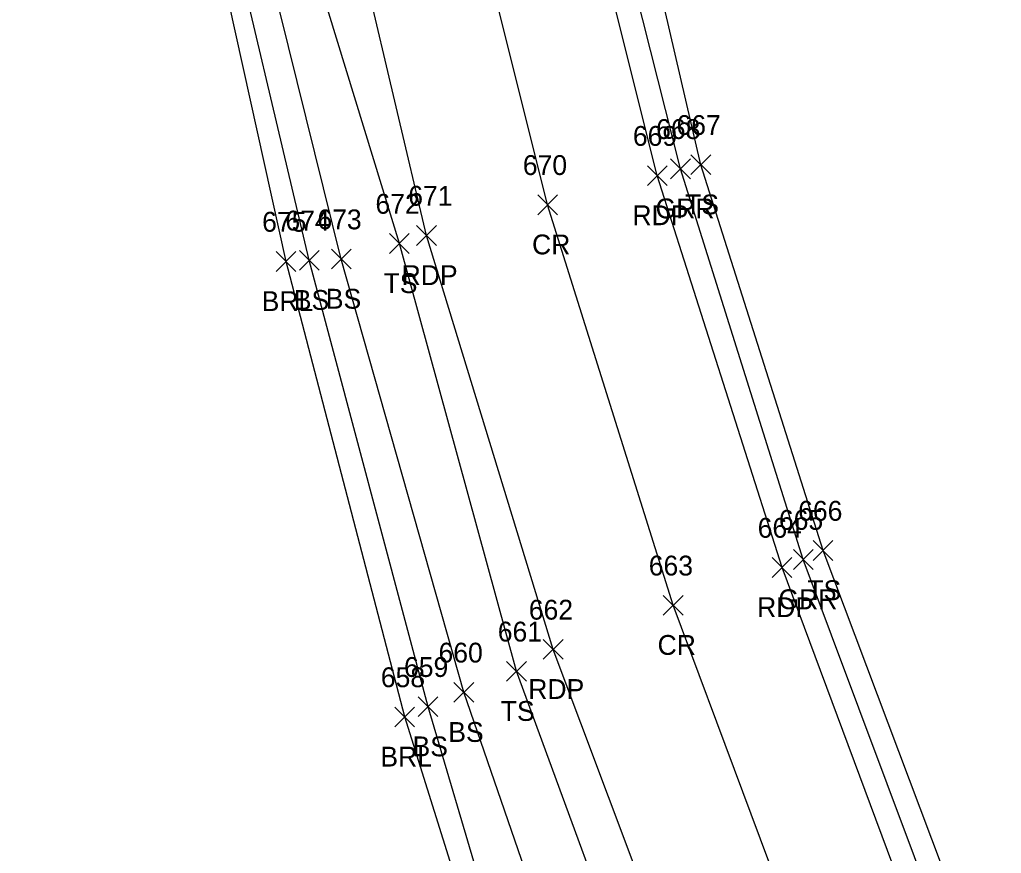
# Model space of a CAD drawing. Extents: x 1879695 to 1880991, y 836466 to 845172.
# Drawn here: x 1879788.6 to 1879887.6, y 844501 to 844585 of the extents above; entities that cross this region are included whole.
import ezdxf

# ---------------------------------------------------------------- set-up
doc = ezdxf.new("R2010")
doc.units = 0
for name, color, linetype in [('L_A', 7, 'Continuous'), ('L_I', 7, 'Continuous'), ('L_TIC', 7, 'Continuous'), ('LABL', 7, 'Continuous'), ('LELB', 7, 'Continuous'), ('P_A', 7, 'Continuous'), ('P_I', 7, 'Continuous'), ('P_TIC', 7, 'Continuous'), ('PET', 7, 'Continuous'), ('PRC', 7, 'Continuous'), ('R_A', 7, 'Continuous'), ('R_I', 7, 'Continuous'), ('R_TIC', 7, 'Continuous'), ('RGR', 7, 'Continuous')]:
    doc.layers.add(name, color=color, linetype=linetype)

msp = doc.modelspace()

# ---------------------------------------------------------------- linework, layer by layer
at = {"layer": 'L_TIC'}
for points in [[(1879856.268, 844569.414), (1879858.268, 844571.414)], [(1879858.268, 844569.414), (1879856.268, 844571.414)], [(1879825.856, 844561.475), (1879827.856, 844563.475)], [(1879827.856, 844561.475), (1879825.856, 844563.475)], [(1879814.427, 844559.662), (1879816.427, 844561.662)], [(1879816.427, 844559.662), (1879814.427, 844561.662)], [(1879816.772, 844559.782), (1879818.772, 844561.782)], [(1879818.772, 844559.782), (1879816.772, 844561.782)], [(1879820.001, 844559.904), (1879822.001, 844561.904)], [(1879822.001, 844559.904), (1879820.001, 844561.904)], [(1879868.595, 844530.526), (1879870.595, 844532.526)], [(1879870.595, 844530.526), (1879868.595, 844532.526)], [(1879837.676, 844518.351), (1879839.676, 844520.351)], [(1879839.676, 844518.351), (1879837.676, 844520.351)], [(1879832.354, 844516.232), (1879834.354, 844518.232)], [(1879834.354, 844516.232), (1879832.354, 844518.232)], [(1879828.748, 844514.782), (1879830.748, 844516.782)], [(1879830.748, 844514.782), (1879828.748, 844516.782)], [(1879826.398, 844513.749), (1879828.398, 844515.749)], [(1879828.398, 844513.749), (1879826.398, 844515.749)]]:
    msp.add_lwpolyline(points, dxfattribs=at)
at = {"layer": 'LABL'}
msp.add_lwpolyline([(1879838.844, 844478.292), (1879827.398, 844514.749), (1879815.427, 844560.662), (1879806.766, 844599.893), (1879795.175, 844646.787), (1879789.744, 844677.989)], dxfattribs=at)
at = {"layer": 'LELB'}
for points in [[(1879840.739, 844478.66), (1879829.748, 844515.782), (1879817.772, 844560.782), (1879808.572, 844599.661), (1879797.58, 844646.674), (1879792.294, 844679.837), (1879789.079, 844683.631), (1879788.581, 844684.774), (1879788.558, 844689.105), (1879790.666, 844689.028), (1879791.227, 844732.995), (1879790.397, 844776.52), (1879790.901, 844833.288), (1879792.574, 844880.834), (1879794.656, 844928.507), (1879796.597, 844970.46), (1879795.452, 845013.86), (1879797.689, 845051.682), (1879797.82, 845087.621), (1879798.32, 845126.29), (1879799.706, 845166.006)], [(1879892.858, 844475.325), (1879883.809, 844493.877), (1879869.595, 844531.526), (1879857.268, 844570.414), (1879848.001, 844610.419), (1879840.978, 844651.693), (1879836.739, 844689.332), (1879832.498, 844735.025), (1879831.422, 844779.249), (1879830.938, 844828.137), (1879831.115, 844883.886), (1879831.784, 844926.928), (1879832.166, 844972.314), (1879832.241, 845014.045), (1879832.594, 845051.892), (1879833.365, 845086.821), (1879834.056, 845125.479), (1879835.582, 845163.134)], [(1880237.645, 844030.169), (1880225.552, 844045.248), (1880203.194, 844067.938), (1880175.04, 844095.38), (1880141.552, 844124.236), (1880111.589, 844152.125), (1880079.671, 844179.091), (1880044.886, 844208.162), (1880013.498, 844237.535), (1880003.345, 844247.815), (1879979.157, 844270.618), (1879948.511, 844300.872), (1879928.971, 844335.674), (1879901.59, 844373.869), (1879881.388, 844405.749), (1879863.368, 844445.075), (1879846.411, 844479.406), (1879833.354, 844517.232), (1879821.001, 844560.904), (1879811.239, 844600.263), (1879800.643, 844646.711), (1879794.198, 844680.159), (1879792.03, 844683.602), (1879789.079, 844683.631)], [(1880243.526, 844023.942), (1880226.641, 844046.282), (1880204.681, 844069.124), (1880177.193, 844097.387), (1880144.147, 844127.373), (1880114.344, 844154.462), (1880082.653, 844181.379), (1880047.531, 844211.782), (1880015.321, 844240.115), (1879982.289, 844271.841), (1879951.965, 844303.04), (1879930.285, 844336.913), (1879904.081, 844374.32), (1879883.922, 844406.902), (1879866.984, 844446.021), (1879852.226, 844482.486), (1879838.676, 844519.351), (1879826.856, 844562.475), (1879815.218, 844600.521)]]:
    msp.add_lwpolyline(points, dxfattribs=at)
at = {"layer": 'P_TIC'}
for points in [[(1879851.877, 844568.319), (1879853.877, 844570.319)], [(1879853.877, 844568.319), (1879851.877, 844570.319)], [(1879840.808, 844565.377), (1879842.808, 844567.377)], [(1879842.808, 844565.377), (1879840.808, 844567.377)], [(1879828.601, 844562.282), (1879830.601, 844564.282)], [(1879830.601, 844562.282), (1879828.601, 844564.282)], [(1879864.456, 844528.814), (1879866.456, 844530.814)], [(1879866.456, 844528.814), (1879864.456, 844530.814)], [(1879853.471, 844525.007), (1879855.471, 844527.007)], [(1879855.471, 844525.007), (1879853.471, 844527.007)], [(1879841.372, 844520.559), (1879843.372, 844522.559)], [(1879843.372, 844520.559), (1879841.372, 844522.559)]]:
    msp.add_lwpolyline(points, dxfattribs=at)
at = {"layer": 'PET'}
for points in [[(1880269.75, 844039.673), (1880250.269, 844065.902), (1880225.972, 844090.312), (1880195.983, 844117.546), (1880162.099, 844148.126), (1880132.616, 844174.702), (1880101.364, 844203.027), (1880066.936, 844232.591), (1880034.498, 844263.161), (1880004.089, 844293.645), (1879978.17, 844323.395), (1879954.458, 844354.819), (1879930.757, 844391.373), (1879912.368, 844423.118), (1879894.175, 844458.904), (1879879.413, 844492.336), (1879865.456, 844529.814), (1879852.877, 844569.319), (1879843.172, 844608.033)], [(1880246.168, 844024.856), (1880229.346, 844048.536), (1880207.668, 844072.229), (1880179.649, 844099.993), (1880146.479, 844130.195), (1880116.3, 844156.757), (1880085.614, 844184.855), (1880050.42, 844215.316), (1880017.65, 844245.828), (1879986.989, 844277.133), (1879959.044, 844308.586), (1879934.196, 844340.79), (1879910.262, 844378.732), (1879891.139, 844411.431), (1879872.359, 844448.445), (1879856.332, 844484.427), (1879842.372, 844521.559), (1879829.601, 844563.282), (1879820.426, 844602.227)]]:
    msp.add_lwpolyline(points, dxfattribs=at)
at = {"layer": 'PRC'}
msp.add_lwpolyline([(1880256.848, 844032.042), (1880238.908, 844056.201), (1880216.704, 844080.653), (1880187.273, 844108.926), (1880154.229, 844138.823), (1880124.193, 844165.482), (1880092.742, 844193.415), (1880058.564, 844223.39), (1880025.993, 844253.924), (1879995.138, 844285.409), (1879968.795, 844316.238), (1879945.09, 844347.911), (1879920.67, 844385.195), (1879902.454, 844417.136), (1879883.724, 844454.205), (1879868.528, 844488.383), (1879854.471, 844526.007), (1879841.808, 844566.377), (1879832.134, 844605.001)], dxfattribs=at)
at = {"layer": 'R_TIC'}
for points in [[(1879854.214, 844569.008), (1879856.214, 844571.008)], [(1879856.214, 844569.008), (1879854.214, 844571.008)], [(1879866.6, 844529.612), (1879868.6, 844531.612)], [(1879868.6, 844529.612), (1879866.6, 844531.612)]]:
    msp.add_lwpolyline(points, dxfattribs=at)
at = {"layer": 'RGR'}
msp.add_lwpolyline([(1880270.9, 844040.926), (1880251.094, 844066.687), (1880226.931, 844091.381), (1880197.342, 844118.121), (1880162.874, 844149.151), (1880133.451, 844175.621), (1880101.915, 844203.718), (1880067.669, 844234.21), (1880035.301, 844264.369), (1880005.303, 844294.796), (1879979.448, 844324.366), (1879956.294, 844356.24), (1879932.566, 844392.559), (1879914.542, 844423.962), (1879896.384, 844459.862), (1879881.659, 844493.029), (1879867.6, 844530.612), (1879855.214, 844570.008), (1879845.358, 844608.98)], dxfattribs=at)

# ---------------------------------------------------------------- texts
at = {"layer": 'L_A'}
for s, p in [('TS', (1879855.677, 844565.414)), ('TS', (1879825.266, 844557.475)), ('BRL', (1879812.97, 844555.662)), ('BS', (1879816.213, 844555.782)), ('BS', (1879819.442, 844555.904)), ('TS', (1879868.004, 844526.526)), ('TS', (1879837.086, 844514.351)), ('BS', (1879831.795, 844512.232)), ('BS', (1879828.189, 844510.782)), ('BRL', (1879824.941, 844509.749))]:
    msp.add_text(s, height=2, dxfattribs=at).set_placement(p)
at = {"layer": 'L_I'}
for s, p in [('667', (1879854.811, 844573.414)), ('672', (1879824.447, 844565.475)), ('675', (1879813.017, 844563.662)), ('674', (1879815.363, 844563.782)), ('673', (1879818.592, 844563.904)), ('666', (1879867.083, 844534.526)), ('661', (1879836.786, 844522.351)), ('660', (1879830.811, 844520.232)), ('659', (1879827.331, 844518.782)), ('658', (1879824.988, 844517.749))]:
    msp.add_text(s, height=2, dxfattribs=at).set_placement(p)
at = {"layer": 'P_A'}
for s, p in [('RDP', (1879850.365, 844564.319)), ('CR', (1879840.241, 844561.377)), ('RDP', (1879827.089, 844558.282)), ('RDP', (1879862.944, 844524.814)), ('CR', (1879852.904, 844521.007)), ('RDP', (1879839.861, 844516.559))]:
    msp.add_text(s, height=2, dxfattribs=at).set_placement(p)
at = {"layer": 'P_I'}
for s, p in [('669', (1879850.412, 844572.319)), ('670', (1879839.312, 844569.377)), ('671', (1879827.758, 844566.282)), ('664', (1879862.999, 844532.814)), ('663', (1879852.014, 844529.007)), ('662', (1879839.916, 844524.559))]:
    msp.add_text(s, height=2, dxfattribs=at).set_placement(p)
at = {"layer": 'R_A'}
for p in [(1879852.702, 844565.008), (1879865.088, 844525.612)]:
    msp.add_text('GRR', height=2, dxfattribs=at).set_placement(p)
at = {"layer": 'R_I'}
for s, p in [('668', (1879852.757, 844573.008)), ('665', (1879865.143, 844533.612))]:
    msp.add_text(s, height=2, dxfattribs=at).set_placement(p)

doc.saveas('drawing.dxf')
